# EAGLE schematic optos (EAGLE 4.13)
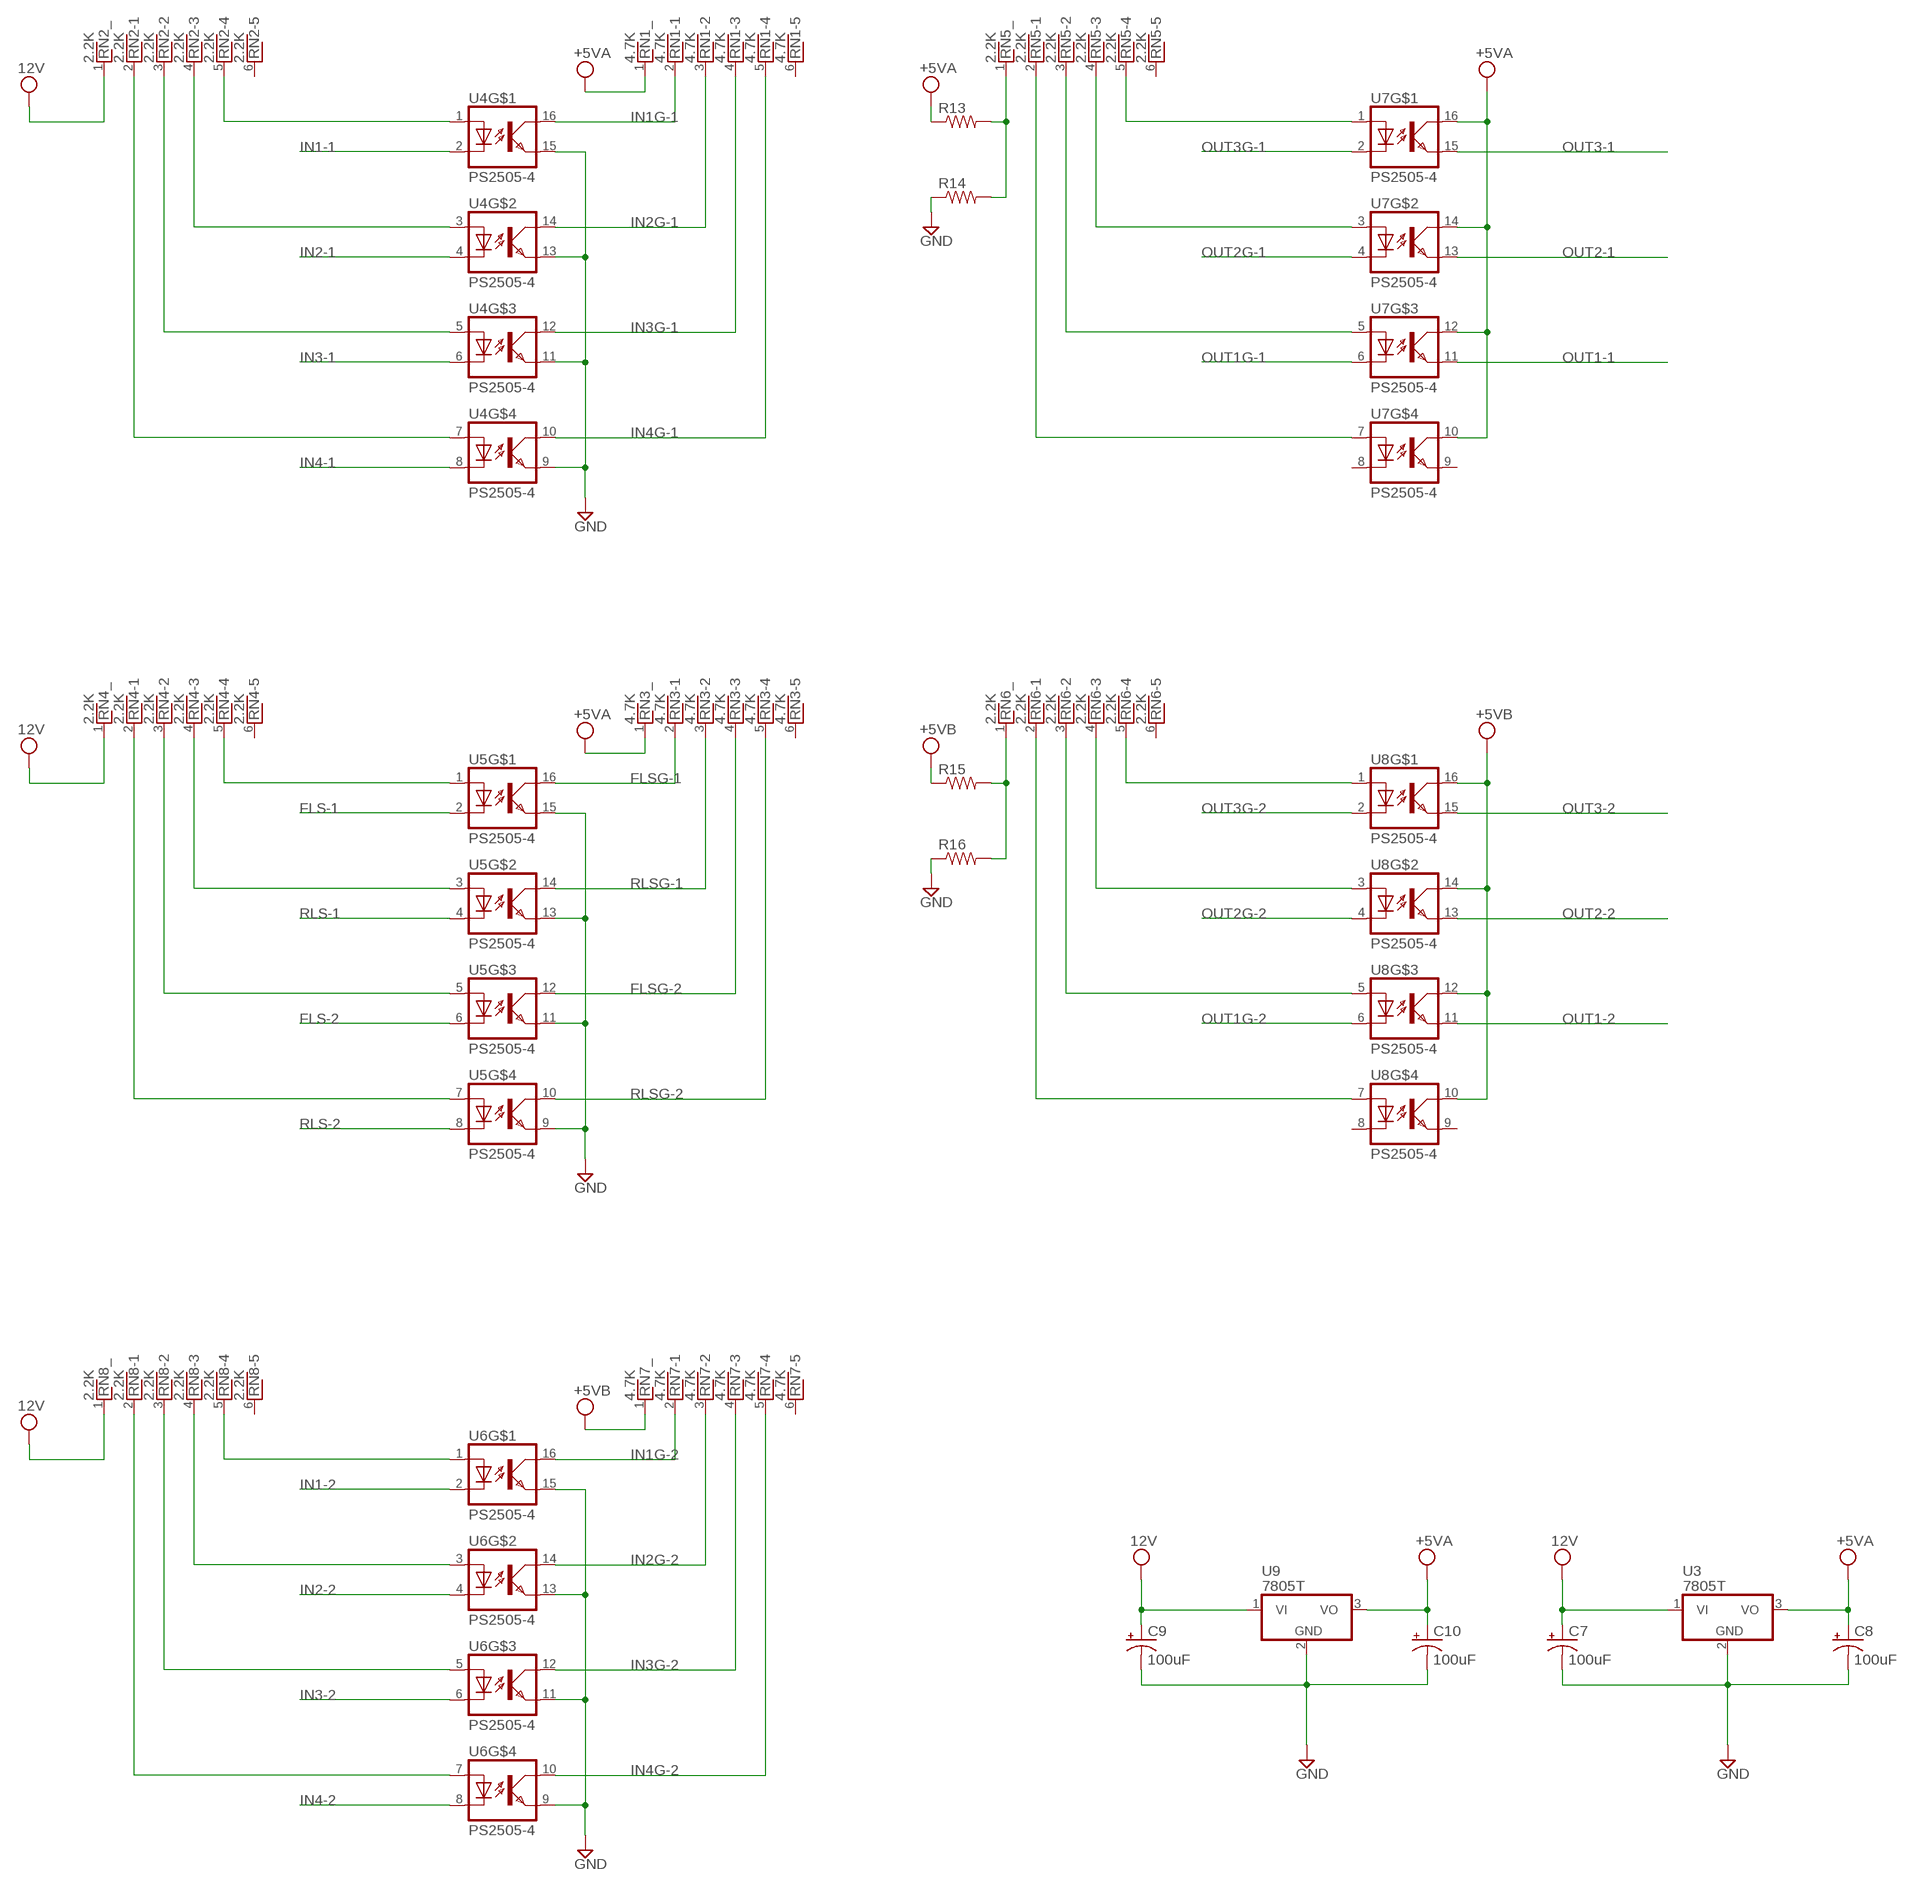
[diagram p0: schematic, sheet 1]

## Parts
C7  100uF  CPOL-USE7.5-16  [E7,5-16]
C8  100uF  CPOL-USE7.5-16  [E7,5-16]
C9  100uF  CPOL-USE7.5-16  [E7,5-16]
C10  100uF  CPOL-USE7.5-16  [E7,5-16]
R13  R-US_0207/10  [0207/10]
R14  R-US_0207/10  [0207/10]
R15  R-US_0207/10  [0207/10]
R16  R-US_0207/10  [0207/10]
RN1  4.7K  RNX5  [RN-6]
RN2  2.2K  RNX5  [RN-6]
RN3  4.7K  RNX5  [RN-6]
RN4  2.2K  RNX5  [RN-6]
RN5  2.2K  RNX5  [RN-6]
RN6  2.2K  RNX5  [RN-6]
RN7  4.7K  RNX5  [RN-6]
RN8  2.2K  RNX5  [RN-6]
U3  7805T  [TO220H]
U4  PS2505-4  [DIL16]
U5  PS2505-4  [DIL16]
U6  PS2505-4  [DIL16]
U7  PS2505-4  [DIL16]
U8  PS2505-4  [DIL16]
U9  7805T  [TO220H]

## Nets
FLS-1: U5.2(C)
FLS-2: U5.6(C)
FLSG-1: RN3.2 U5.16(COL)
FLSG-2: RN3.4 U5.12(COL)
GND: C7.- C8.- C9.- C10.- R14.1 R16.1 U3.2(GND) U4.9(EMIT) U4.11(EMIT) U4.13(EMIT) U4.15(EMIT) U5.9(EMIT) U5.11(EMIT) U5.13(EMIT) U5.15(EMIT) U6.9(EMIT) U6.11(EMIT) U6.13(EMIT) U6.15(EMIT) U9.2(GND)
IN1-1: U4.2(C)
IN1-2: U6.2(C)
IN1G-1: RN1.2 U4.16(COL)
IN1G-2: RN7.2 U6.16(COL)
IN2-1: U4.4(C)
IN2-2: U6.4(C)
IN2G-1: RN1.3 U4.14(COL)
IN2G-2: RN7.3 U6.14(COL)
IN3-1: U4.6(C)
IN3-2: U6.6(C)
IN3G-1: RN1.4 U4.12(COL)
IN3G-2: RN7.4 U6.12(COL)
IN4-1: U4.8(C)
IN4-2: U6.8(C)
IN4G-1: RN1.5 U4.10(COL)
IN4G-2: RN7.5 U6.10(COL)
N$1: RN2.5 U4.1(A)
N$2: RN2.4 U4.3(A)
N$3: RN2.3 U4.5(A)
N$4: RN2.2 U4.7(A)
N$5: RN5.5 U7.1(A)
N$6: RN5.4 U7.3(A)
N$7: RN5.3 U7.5(A)
N$8: RN5.2 U7.7(A)
N$9: RN4.5 U5.1(A)
N$10: RN4.4 U5.3(A)
N$11: RN4.3 U5.5(A)
N$12: RN4.2 U5.7(A)
N$13: RN6.5 U8.1(A)
N$14: RN6.4 U8.3(A)
N$15: RN6.3 U8.5(A)
N$16: RN6.2 U8.7(A)
N$17: RN8.5 U6.1(A)
N$18: RN8.4 U6.3(A)
N$19: RN8.3 U6.5(A)
N$20: RN8.2 U6.7(A)
N$21: R13.2 R14.2 RN5.1
N$22: R15.2 R16.2 RN6.1
OUT1-1: U7.11(EMIT)
OUT1-2: U8.11(EMIT)
OUT1G-1: U7.6(C)
OUT1G-2: U8.6(C)
OUT2-1: U7.13(EMIT)
OUT2-2: U8.13(EMIT)
OUT2G-1: U7.4(C)
OUT2G-2: U8.4(C)
OUT3-1: U7.15(EMIT)
OUT3-2: U8.15(EMIT)
OUT3G-1: U7.2(C)
OUT3G-2: U8.2(C)
RLS-1: U5.4(C)
RLS-2: U5.8(C)
RLSG-1: RN3.3 U5.14(COL)
RLSG-2: RN3.5 U5.10(COL)
VCC: C7.+ C8.+ C9.+ C10.+ R13.1 R15.1 RN1.1 RN2.1 RN3.1 RN4.1 RN7.1 RN8.1 U3.1(VI) U3.3(VO) U7.10(COL) U7.12(COL) U7.14(COL) U7.16(COL) U8.10(COL) U8.12(COL) U8.14(COL) U8.16(COL) U9.1(VI) U9.3(VO) ; supply symbol labelled 12V, +5VA, +5VB
Unconnected: RN1.6 RN2.6 RN3.6 RN4.6 RN5.6 RN6.6 RN7.6 RN8.6 U7.8(C) U7.9(EMIT) U8.8(C) U8.9(EMIT)

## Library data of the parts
C7-C10 = rcl:CPOL-US: POLARIZED CAPACITOR, American symbol
R13-R16 = rcl:R-US_: RESISTOR, American symbol
RN1-RN8 = resistor-net:RNX5: RESISTOR NETWORK
U3 U9 = linear:78*: Positive VOLTAGE REGULATOR
U4-U8 = optocoupler:PS2505-4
